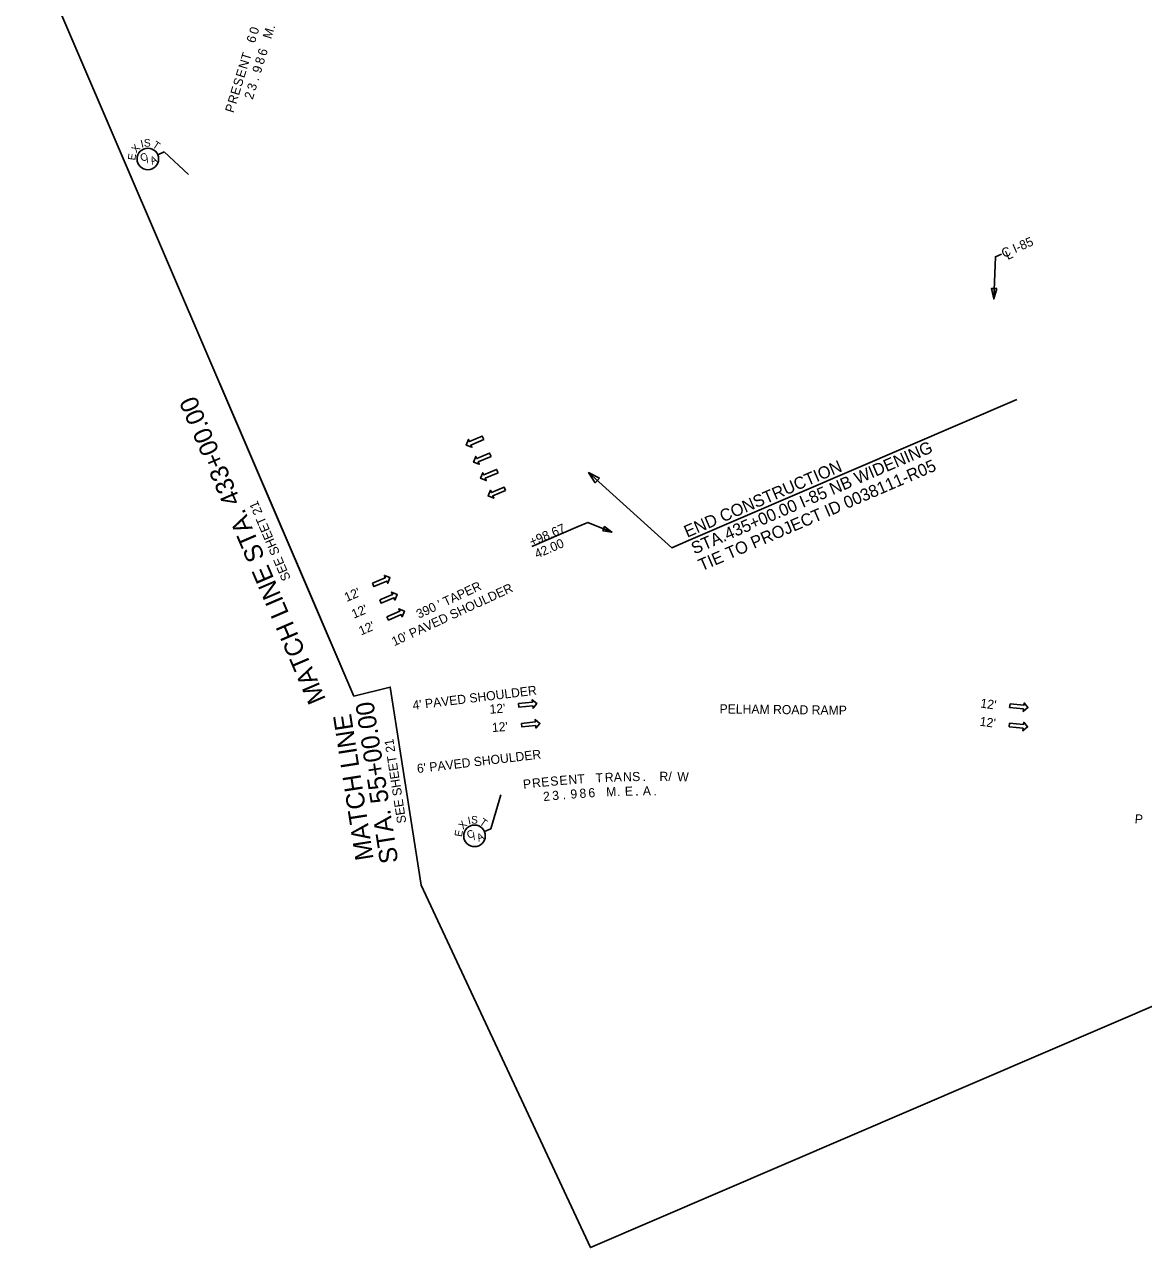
# Model space of a CAD drawing. Extents: x 1621035 to 1623496, y 1102384 to 1103996.
# Drawn here: x 1621083 to 1621820, y 1102384 to 1103189 of the extents above; entities that cross this region are included whole.
import ezdxf

# ---------------------------------------------------------------- set-up
doc = ezdxf.new("R2010")
doc.units = 0
for name, color, linetype in [('RD_EX_DV_TX_Prop', 7, 'Continuous'), ('RD_EX_GuardRail', 7, 'Continuous'), ('RD_EX_RailRoad', 7, 'Continuous'), ('RD_EX_RW', 7, 'Continuous'), ('RD_HC_Data_Tic_Rel', 7, 'Continuous'), ('RD_PD_Final_TX', 7, 'Continuous'), ('RD_Sketch10', 7, 'Continuous')]:
    doc.layers.add(name, color=color, linetype=linetype)

msp = doc.modelspace()

# ---------------------------------------------------------------- linework, layer by layer
at = {"layer": 'RD_EX_GuardRail'}
for points in [[(1621385.51, 1102915.75), (1621384.57, 1102917.95), (1621376.14, 1102914.33), (1621375.5, 1102915.83), (1621374.01, 1102912.12), (1621377.73, 1102910.63), (1621377.08, 1102912.13)], [(1621390.3, 1102904.58), (1621389.36, 1102906.79), (1621380.93, 1102903.17), (1621380.29, 1102904.67), (1621378.8, 1102900.95), (1621382.52, 1102899.47), (1621381.88, 1102900.96)], [(1621394.91, 1102893.84), (1621393.97, 1102896.04), (1621385.54, 1102892.43), (1621384.9, 1102893.92), (1621383.41, 1102890.21), (1621387.13, 1102888.72), (1621386.49, 1102890.22)], [(1621399.89, 1102882.25), (1621398.94, 1102884.46), (1621390.51, 1102880.84), (1621389.87, 1102882.34), (1621388.39, 1102878.62), (1621392.1, 1102877.14), (1621391.46, 1102878.63)], [(1621312.3, 1102821.23), (1621313.25, 1102819.03), (1621321.67, 1102822.65), (1621322.32, 1102821.15), (1621323.8, 1102824.87), (1621320.08, 1102826.35), (1621320.73, 1102824.85)], [(1621317.03, 1102810.21), (1621317.98, 1102808), (1621326.41, 1102811.62), (1621327.05, 1102810.12), (1621328.53, 1102813.84), (1621324.82, 1102815.32), (1621325.46, 1102813.83)], [(1621321.77, 1102799.18), (1621322.71, 1102796.98), (1621331.14, 1102800.59), (1621331.78, 1102799.1), (1621333.27, 1102802.81), (1621329.55, 1102804.3), (1621330.19, 1102802.8)], [(1621408.44, 1102742.02), (1621408.68, 1102739.63), (1621417.81, 1102740.54), (1621417.97, 1102738.92), (1621420.5, 1102742.01), (1621417.41, 1102744.54), (1621417.57, 1102742.92)], [(1621731.93, 1102741.94), (1621731.66, 1102739.55), (1621740.77, 1102738.5), (1621740.59, 1102736.89), (1621743.72, 1102739.37), (1621741.23, 1102742.51), (1621741.05, 1102740.89)], [(1621410.37, 1102729.01), (1621410.61, 1102726.62), (1621419.73, 1102727.52), (1621419.9, 1102725.9), (1621422.43, 1102729), (1621419.34, 1102731.53), (1621419.5, 1102729.91)], [(1621731.67, 1102729.2), (1621731.39, 1102726.81), (1621740.51, 1102725.77), (1621740.32, 1102724.15), (1621743.45, 1102726.64), (1621740.97, 1102729.77), (1621740.78, 1102728.15)]]:
    msp.add_lwpolyline(points, close=True, dxfattribs=at)
at = {"layer": 'RD_EX_RailRoad'}
msp.add_line((1621344.3, 1102622.52), (1621324.02, 1102752.88), dxfattribs=at)
msp.add_lwpolyline([(1621300.09, 1102746.85), (1621270.78, 1102815.13), (1621211.62, 1102952.97)], dxfattribs=at)
at = {"layer": 'RD_EX_RW'}
for p, q in [((1621736.36, 1102942), (1621520.22, 1102849.23)), ((1621447.69, 1102858.46), (1621417.13, 1102845.35))]:
    msp.add_line(p, q, dxfattribs=at)
for points in [[(1621520.22, 1102849.23), (1621509.35, 1102844.56), (1621454.57, 1102894.01)], [(1621447.69, 1102858.46), (1621454.02, 1102861.18), (1621469.91, 1102854.89)]]:
    msp.add_lwpolyline(points, dxfattribs=at)
for points in [[(1621461.69, 1102890.37), (1621454.57, 1102894.01), (1621458.92, 1102887.29)], [(1621463.95, 1102855.58), (1621469.91, 1102854.89), (1621465.09, 1102858.47)]]:
    msp.add_lwpolyline(points, close=True, dxfattribs=at)
at = {"layer": 'RD_HC_Data_Tic_Rel'}
msp.add_lwpolyline([(1621721.3, 1103008.49), (1621722.26, 1103036.01), (1621726.3, 1103037.74)], dxfattribs=at)
msp.add_lwpolyline([(1621723.18, 1103015.02), (1621719.74, 1103015.14), (1621721.22, 1103008.19)], close=True, dxfattribs=at)
at = {"layer": 'RD_PD_Final_TX'}
msp.add_lwpolyline([(1621300.09, 1102746.85), (1621324.02, 1102752.88), (1621344.3, 1102622.52), (1621455.74, 1102384.16), (1622813.61, 1102966.94), (1622454.69, 1103803.24), (1622329.06, 1103749.66), (1622314.99, 1103780.87), (1621083.19, 1103252.2)], close=True, dxfattribs=at)
msp.add_lwpolyline([(1621300.09, 1102746.85), (1621324.02, 1102752.88), (1621344.3, 1102622.52), (1621455.74, 1102384.16), (1622813.61, 1102966.94), (1622454.69, 1103803.24), (1622329.06, 1103749.66), (1622314.99, 1103780.87), (1621083.19, 1103252.2)], close=True, dxfattribs=at)
at = {"layer": 'RD_Sketch10'}
for p, q in [((1621170.94, 1103103.13), (1621175.14, 1103104.93)), ((1621175.14, 1103104.93), (1621191.23, 1103090.14)), ((1621390.16, 1102659.6), (1621396.82, 1102681.91)), ((1621385.96, 1102657.79), (1621390.16, 1102659.6))]:
    msp.add_line(p, q, dxfattribs=at)
for centre in [(1621164.42, 1103100.33), (1621379.45, 1102654.99)]:
    msp.add_circle(centre, 7.08, dxfattribs=at)

# ---------------------------------------------------------------- texts
at = {"layer": 'RD_EX_DV_TX_Prop'}
for s, rotation, p in [('6', 72.96918, (1621234.86, 1103176.17)), ('0', 72.96918, (1621236.59, 1103181.81)), ('M', 72.96918, (1621245.62, 1103178.87)), ('.', 72.96918, (1621247.72, 1103185.72)), ('N', 72.96918, (1621229.59, 1103158.96)), ('T', 72.96918, (1621231.31, 1103164.58)), ('8', 72.96918, (1621240.47, 1103162.05)), ('6', 72.96918, (1621242.19, 1103167.65)), ('E', 72.96918, (1621227.84, 1103153.24)), ('9', 72.96918, (1621238.71, 1103156.31)), ('S', 72.96918, (1621226.07, 1103147.48)), ('3', 72.96918, (1621235.2, 1103144.83)), ('.', 72.96918, (1621237.18, 1103151.29)), ('R', 72.96918, (1621222.56, 1103136.01)), ('E', 72.96918, (1621224.32, 1103141.77)), ('2', 72.96918, (1621233.44, 1103139.1)), ('P', 72.96918, (1621220.8, 1103130.27)), ('P', 6.78169, (1621411.73, 1102685.88)), ('R', 6.30718, (1621417.67, 1102686.57)), ('E', 5.83268, (1621423.63, 1102687.22)), ('S', 5.35817, (1621429.55, 1102687.82)), ('E', 4.88366, (1621435.53, 1102688.37)), ('N', 4.40916, (1621441.46, 1102688.87)), ('T', 3.93465, (1621447.3, 1102689.31)), ('T', 2.98564, (1621459.22, 1102690.06)), ('R', 2.51113, (1621465.31, 1102690.37)), ('A', 2.03663, (1621471.16, 1102690.62)), ('N', 1.56212, (1621477.25, 1102690.83)), ('S', 1.08762, (1621483.22, 1102690.98)), ('.', 0.61311, (1621490.1, 1102691.1)), ('R', 359.6641, (1621501.15, 1102691.15)), ('/', 359.18959, (1621507.01, 1102691.11)), ('W', 358.71509, (1621512.84, 1102691.02)), ('2', 5.81691, (1621424.91, 1102677.81)), ('3', 5.3361, (1621430.85, 1102678.4)), ('9', 4.37448, (1621442.76, 1102679.44)), ('8', 3.89367, (1621448.72, 1102679.89)), ('6', 3.41286, (1621454.54, 1102680.27)), ('M', 2.45124, (1621466.21, 1102680.91)), ('E', 1.48962, (1621478.43, 1102681.36)), ('A', 0.528, (1621490.24, 1102681.6)), ('.', 0.04719, (1621497.23, 1102681.65)), ('.', 4.85529, (1621437.56, 1102679.01)), ('.', 1.97043, (1621473.34, 1102681.19)), ('.', 1.00881, (1621485.28, 1102681.52)), ('P', 354.86309, (1621813.81, 1102663.37))]:
    msp.add_text(s, height=6, rotation=rotation, dxfattribs=at).set_placement(p)
at = {"layer": 'RD_EX_RailRoad'}
for s, height, rotation, p in [('MATCH LINE STA. 433+00.00', 12, 113.22835, (1621281.75, 1102744.85)), ('SEE SHEET 21', 6, 113.22835, (1621258.61, 1102824.3)), ('STA. 55+00.00', 12, 98.84251, (1621329.3, 1102637.75)), ('MATCH LINE', 12, 98.84251, (1621313.06, 1102639.81)), ('SEE SHEET 21', 6, 98.84251, (1621334.58, 1102663.69))]:
    msp.add_text(s, height=height, rotation=rotation, dxfattribs=at).set_placement(p)
at = {"layer": 'RD_EX_RW'}
for s, height, rotation, p in [('STA.435+00.00 I-85 NB WIDENING', 8, 23.22998, (1621524.16, 1102840.04)), ('END CONSTRUCTION', 8, 23.22998, (1621519.43, 1102851.07)), ('TIE TO PROJECT ID 0038111-R05', 8, 23.22998, (1621528.89, 1102829.01)), ('+98.67', 6, 23.22672, (1621417.13, 1102845.35)), ('42.00', 6, 23.22672, (1621420.54, 1102837.4)), ("10' PAVED SHOULDER", 6, 24.76409, (1621326.59, 1102779.68)), ("390 ' TAPER", 6, 24.99662, (1621342.81, 1102797.79)), ("12'", 6, 23.23465, (1621295.29, 1102808.83)), ("12'", 6, 23.23465, (1621300.03, 1102797.8)), ("12'", 6, 23.23465, (1621304.76, 1102786.78)), ("4' PAVED SHOULDER", 6, 7.01014, (1621339.05, 1102737.9)), ("12'", 6, 4.41213, (1621389.57, 1102735.3)), ("12'", 6, 352.1934, (1621712.12, 1102739.46)), ("12'", 6, 352.1934, (1621711.66, 1102727.49)), ("12'", 6, 4.41213, (1621391.13, 1102723.24)), ("6' PAVED SHOULDER", 6, 6.71625, (1621341.9, 1102696.26))]:
    msp.add_text(s, height=height, rotation=rotation, dxfattribs=at).set_placement(p)
at = {"layer": 'RD_HC_Data_Tic_Rel'}
for s, rotation, p in [('C I-85', 23.22168, (1621727.83, 1103035.18)), ('L', 23.22168, (1621730.35, 1103033.83)), ('PELHAM ROAD RAMP', 359.35269, (1621540.69, 1102735.57))]:
    msp.add_text(s, height=6, rotation=rotation, dxfattribs=at).set_placement(p)
at = {"layer": 'RD_Sketch10'}
for s, rotation, p in [('X', 48.32187, (1621156.82, 1103103.94)), ('I', 13.1604, (1621160.28, 1103107.67)), ('S', 1.43991, (1621161.86, 1103108.35)), ('T', 326.27843, (1621166.95, 1103108.37)), ('E', 81.80899, (1621156.09, 1103099.15)), ('C', 23.2251, (1621160.58, 1103098.26)), ('/', 23.2251, (1621164.13, 1103097.49)), ('A', 23.2251, (1621167.12, 1103096.43)), ('I', 11.20824, (1621375.56, 1102662.46)), ('S', 359.48775, (1621377.16, 1102663.1)), ('T', 324.32628, (1621382.24, 1102662.94)), ('E', 79.85684, (1621371.07, 1102654.09)), ('X', 46.36972, (1621371.97, 1102658.86)), ('C', 23.2251, (1621375.6, 1102652.92)), ('/', 23.2251, (1621379.15, 1102652.15)), ('A', 23.2251, (1621382.14, 1102651.09))]:
    msp.add_text(s, height=5, rotation=rotation, dxfattribs=at).set_placement(p)

doc.saveas('drawing.dxf')
